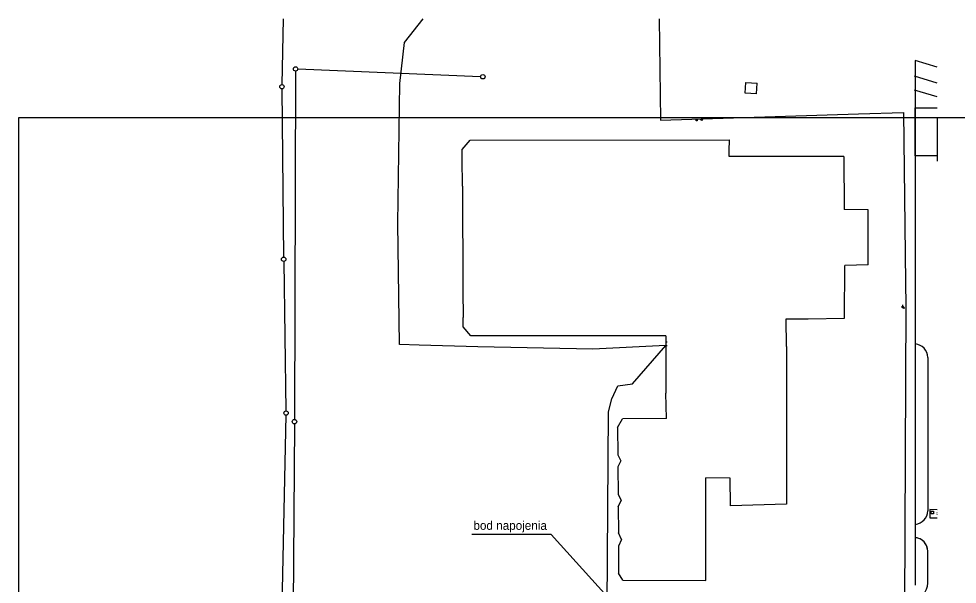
# Model space of a CAD drawing. Extents: x -264205 to -263744, y -1242450 to -1242050.
# Drawn here: x -264164.5 to -263949.9, y -1242179.2 to -1242050 of the extents above; entities that cross this region are included whole.
import ezdxf

# ---------------------------------------------------------------- set-up
doc = ezdxf.new("R2010")
doc.units = 0
for name, color, linetype in [('KFA_JESTV_IS_DSP', 7, 'Continuous'), ('KFA_SITUACIA_DSP', 7, 'Continuous'), ('KFA_TELEKOM_POVODNA_TRASA', 7, 'Continuous'), ('POPIS', 7, 'Continuous'), ('RAM_NA_TLAC_A3_1-1000', 7, 'Continuous')]:
    doc.layers.add(name, color=color, linetype=linetype)

msp = doc.modelspace()

# ---------------------------------------------------------------- linework, layer by layer
at = {"layer": 'KFA_JESTV_IS_DSP'}
for p, q in [((-264103.97, -1242050), (-264104.29, -1242065.03)), ((-264018.04, -1242050), (-264017.72, -1242073.15)), ((-264101.18, -1242061.97), (-264101.42, -1242141.58)), ((-264058.85, -1242063.24), (-264100.68, -1242061.49)), ((-264104.29, -1242066.03), (-264103.9, -1242104.47)), ((-264017.72, -1242073.15), (-263972.45, -1242071.72)), ((-263972.45, -1242071.72), (-263962.12, -1242071.44)), ((-263962.12, -1242071.44), (-263961.71, -1242110.25)), ((-264008.43, -1242073.18), (-264008.14, -1242072.95)), ((-264008.41, -1242072.62), (-264008.16, -1242072.62)), ((-264008.29, -1242072.87), (-264008.29, -1242072.62)), ((-264103.89, -1242105.47), (-264103.36, -1242139.62)), ((-263961.71, -1242110.25), (-263961.58, -1242115.55)), ((-263962.48, -1242115.97), (-263962.19, -1242115.74)), ((-263962.46, -1242115.42), (-263962.21, -1242115.42)), ((-263962.34, -1242115.67), (-263962.34, -1242115.42)), ((-263961.58, -1242115.55), (-263962, -1242192.92)), ((-264016.21, -1242123.92), (-264016.51, -1242123.92)), ((-264016.51, -1242123.92), (-264016.5, -1242124.67)), ((-264016.5, -1242124.67), (-264016.2, -1242124.67)), ((-264103.36, -1242140.62), (-264104.36, -1242188.14)), ((-264101.42, -1242142.58), (-264101.75, -1242191.96)), ((-263956.13, -1242162.18), (-263956.16, -1242164.04)), ((-263954.47, -1242162.2), (-263956.13, -1242162.18)), ((-263956.16, -1242164.04), (-263954.47, -1242164.06)), ((-263955.83, -1242163.15), (-263955.83, -1242162.57)), ((-263955.83, -1242162.57), (-263955.28, -1242162.57)), ((-263955.28, -1242163.15), (-263955.83, -1242163.15)), ((-263955.28, -1242162.57), (-263955.28, -1242163.15)), ((-263954.47, -1242162.89), (-263954.54, -1242162.89)), ((-263954.47, -1242163.25), (-263954.54, -1242163.26))]:
    msp.add_line(p, q, dxfattribs=at)
for centre, radius in [((-264101.18, -1242061.47), 0.5), ((-264058.35, -1242063.26), 0.5), ((-264104.3, -1242065.53), 0.5), ((-264009.44, -1242073.2), 0.125), ((-264008.29, -1242073.06), 0.188), ((-264103.89, -1242104.97), 0.5), ((-263962.34, -1242115.86), 0.188), ((-263962.11, -1242116.08), 0.125), ((-264103.35, -1242140.12), 0.5), ((-264101.42, -1242142.08), 0.5)]:
    msp.add_circle(centre, radius, dxfattribs=at)
at = {"layer": 'KFA_SITUACIA_DSP'}
for p, q in [((-263959.47, -1242059.53), (-263959.47, -1242179.48)), ((-263954.47, -1242061.03), (-263959.47, -1242059.53)), ((-263998.36, -1242066.98), (-263998.17, -1242064.57)), ((-263998.17, -1242064.57), (-263995.59, -1242064.72)), ((-263995.79, -1242067.14), (-263995.59, -1242064.72)), ((-263995.79, -1242067.14), (-263998.36, -1242066.98)), ((-263959.47, -1242071.38), (-263959.47, -1242070.38)), ((-263959.47, -1242070.38), (-263954.47, -1242070.38)), ((-263959.47, -1242076.38), (-263959.47, -1242071.38)), ((-264063.06, -1242079.88), (-264061.28, -1242077.73)), ((-264061.28, -1242077.73), (-264001.95, -1242077.64)), ((-264002.01, -1242080.21), (-264001.95, -1242077.64)), ((-263959.47, -1242081.31), (-263959.47, -1242076.38)), ((-264063.05, -1242082.02), (-264063.06, -1242079.88)), ((-264002.04, -1242081.51), (-264002.01, -1242080.21)), ((-264063.02, -1242088.27), (-264063.05, -1242082.02)), ((-263975.78, -1242081.51), (-264002.04, -1242081.51)), ((-263975.78, -1242081.51), (-263975.68, -1242093.61)), ((-263954.47, -1242081.31), (-263959.47, -1242081.31)), ((-264063.02, -1242088.27), (-264062.89, -1242112.12)), ((-263970.24, -1242093.63), (-263975.68, -1242093.61)), ((-263970.22, -1242106.22), (-263970.24, -1242093.63)), ((-263975.61, -1242118.44), (-263975.57, -1242106.38)), ((-263970.22, -1242106.22), (-263975.57, -1242106.38)), ((-264062.89, -1242112.12), (-264062.88, -1242118.3)), ((-264062.88, -1242120.44), (-264062.88, -1242118.3)), ((-263989, -1242118.61), (-263983.93, -1242118.61)), ((-263988.88, -1242124.89), (-263989, -1242118.61)), ((-263983.93, -1242118.61), (-263975.61, -1242118.44)), ((-264061.11, -1242122.5), (-264062.88, -1242120.44)), ((-264016.48, -1242122.48), (-264061.11, -1242122.5)), ((-264016.48, -1242122.48), (-264016.47, -1242135.53)), ((-263988.88, -1242124.89), (-263988.91, -1242160.93)), ((-263959.47, -1242124.32), (-263959.47, -1242124.32)), ((-263956.62, -1242127.42), (-263956.62, -1242162.45)), ((-264016.38, -1242141.37), (-264016.47, -1242135.53)), ((-264027.55, -1242143.43), (-264026.42, -1242141.41)), ((-264016.38, -1242141.37), (-264026.42, -1242141.41)), ((-264027.55, -1242143.43), (-264027.5, -1242149.68)), ((-264027.5, -1242149.68), (-264026.79, -1242151.05)), ((-264026.79, -1242151.05), (-264027.48, -1242152.43)), ((-264027.48, -1242152.43), (-264027.43, -1242158.63)), ((-264007.37, -1242157.14), (-264007.36, -1242154.93)), ((-264001.8, -1242154.96), (-264007.36, -1242154.93)), ((-264001.73, -1242161.29), (-264001.8, -1242154.96)), ((-264007.34, -1242178.42), (-264007.37, -1242157.14)), ((-264027.43, -1242158.63), (-264026.72, -1242160.07)), ((-264027.41, -1242161.52), (-264026.72, -1242160.07)), ((-264027.41, -1242161.52), (-264027.36, -1242167.48)), ((-263988.91, -1242160.93), (-264001.73, -1242161.29)), ((-263959.47, -1242165.55), (-263959.47, -1242165.55)), ((-264026.65, -1242168.99), (-264027.36, -1242167.48)), ((-263959.47, -1242168.58), (-263959.47, -1242168.58)), ((-264026.65, -1242168.99), (-264027.34, -1242170.52)), ((-264027.34, -1242170.52), (-264027.29, -1242176.68)), ((-263956.62, -1242178.98), (-263956.62, -1242171.65)), ((-264026.37, -1242178.31), (-264027.29, -1242176.68)), ((-264026.37, -1242178.31), (-264007.34, -1242178.42)), ((-263956.62, -1242178.98), (-263956.62, -1242178.98))]:
    msp.add_line(p, q, dxfattribs=at)
for points in [[(-263954.47, -1242061.03), (-263959.47, -1242059.53)], [(-263954.47, -1242064.69), (-263959.61, -1242063.14)], [(-263954.47, -1242067.82), (-263959.61, -1242066.28)], [(-263956.62, -1242178.98), (-263956.62, -1242171.63), (-263956.64, -1242171.26), (-263956.71, -1242170.89), (-263956.87, -1242170.41), (-263957.16, -1242169.89), (-263957.43, -1242169.55), (-263957.71, -1242169.29), (-263958.08, -1242169.02), (-263958.45, -1242168.83), (-263958.84, -1242168.69), (-263959.06, -1242168.64), (-263959.27, -1242168.6), (-263959.47, -1242168.58)]]:
    msp.add_lwpolyline(points, dxfattribs=at)
for centre, radius, start, end in [((-263959.74, -1242127.43), 3.12, 0.1518, 85.0363), ((-263959.74, -1242162.44), 3.12, 274.9637, 359.8482), ((-263959.67, -1242171.63), 3.05, 359.6441, 86.2155), ((-263960.12, -1242178.98), 3.5, 270, 0)]:
    msp.add_arc(centre, radius, start, end, dxfattribs=at)
at = {"layer": 'KFA_TELEKOM_POVODNA_TRASA'}
for p, q in [((-264076.26, -1242055.4), (-264072, -1242050)), ((-264077.35, -1242064.76), (-264076.26, -1242055.4)), ((-264077.8, -1242096.77), (-264077.35, -1242064.76)), ((-264077.43, -1242124.43), (-264077.8, -1242096.77)), ((-264072.89, -1242124.56), (-264077.43, -1242124.43)), ((-264059.47, -1242124.95), (-264072.89, -1242124.56)), ((-264033.2, -1242125.52), (-264059.47, -1242124.95)), ((-264016.5, -1242124.67), (-264033.2, -1242125.52)), ((-264024.13, -1242133.46), (-264016.5, -1242124.67)), ((-264028.85, -1242136.85), (-264027.51, -1242133.87)), ((-264027.51, -1242133.87), (-264024.13, -1242133.46)), ((-264029.59, -1242139.82), (-264028.85, -1242136.85)), ((-264029.91, -1242188.32), (-264029.59, -1242139.82))]:
    msp.add_line(p, q, dxfattribs=at)
at = {"layer": 'POPIS'}
for p, q in [((-264042.71, -1242167.9), (-264060.85, -1242167.9)), ((-264029.87, -1242182.08), (-264042.71, -1242167.9))]:
    msp.add_line(p, q, dxfattribs=at)
at = {"layer": 'RAM_NA_TLAC_A3_1-1000'}
msp.add_line((-263954.47, -1242072.57), (-263954.47, -1242082.57), dxfattribs=at)
msp.add_lwpolyline([(-264164.47, -1242072.57), (-263744.47, -1242072.57), (-263744.47, -1242369.57), (-264164.47, -1242369.57)], close=True, dxfattribs=at)

# ---------------------------------------------------------------- texts
at = {"layer": 'POPIS'}
msp.add_text('bod napojenia', height=2, dxfattribs=at).set_placement((-264060.5, -1242166.8))

doc.saveas('drawing.dxf')
